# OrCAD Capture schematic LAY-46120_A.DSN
size A3; rev: 00; note: JN5189 USB DONGLE
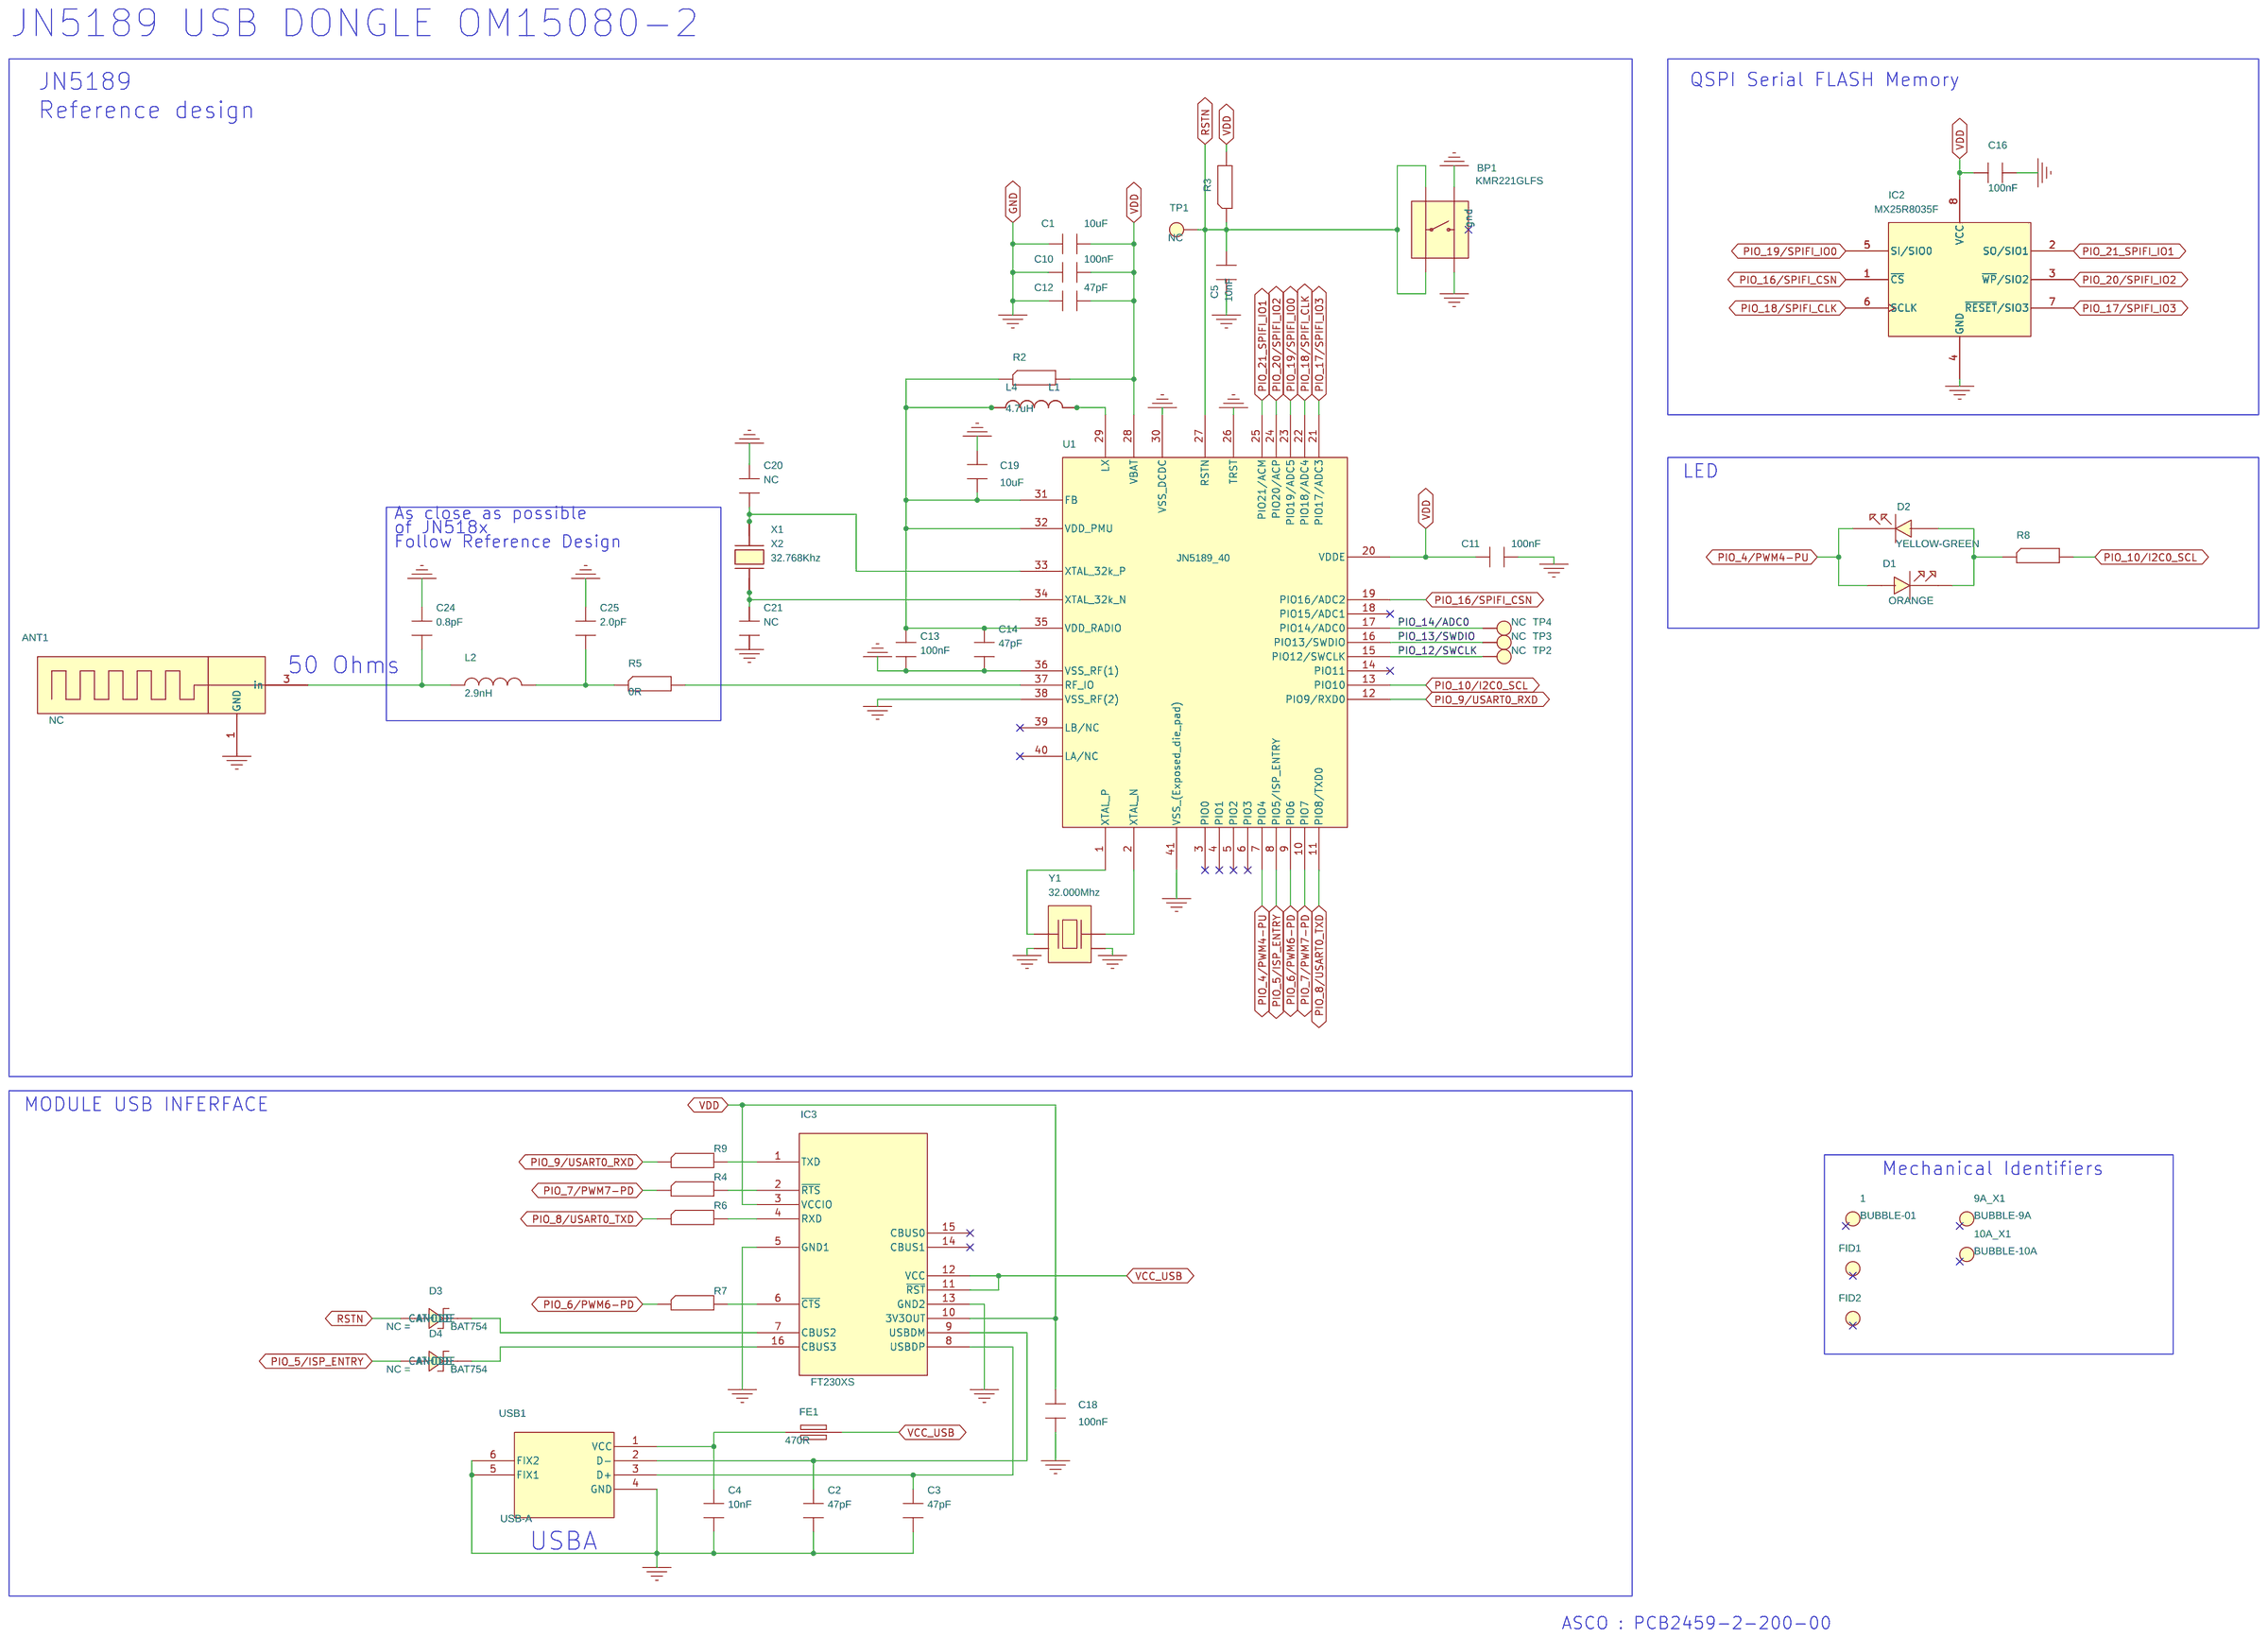
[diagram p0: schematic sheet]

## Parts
1  BUBBLE-01  [BUBBLE_DIAM8]
9A_X1  BUBBLE-9A  [BUBBLE_DIAM8]
10A_X1  BUBBLE-10A  [BUBBLE_DIAM8]
ANT1  NC  [pcb_ant_apps]
BP1  KMR221GLFS  [BP_KMR]
C1  10uF  [C0805]
C2  47pF  [C0402]
C3  47pF  [C0402]
C4  10nF  [C0402]
C5  10nF  [C0402]
C10  100nF  [C0402]
C11  100nF  [C0402]
C12  47pF  [C0402]
C13  100nF  [C0402]
C14  47pF  [C0402]
C16  100nF  [C0402]
C18  100nF  [C0402]
C19  10uF  [C0805]
C20  NC  [C0402]
C21  NC  [C0402]
C24  0.8pF  [C0402]
C25  2.0pF  [C0402]
D1  ORANGE  [LED_0603_A_K]
D2  YELLOW-GREEN  [LED_0603_A_K]
D3  BAT754  [SOT23]
D4  BAT754  [SOT23]
FE1  470R  [blm18]
FID1  NC  [FID1]
FID2  NC  [FID1]
IC2  MX25R8035F  [SOP8_127_200]
IC3  FT230XS  [jedec_mo137_ab_ssop16]
L1  4,7uH_NC  [IND_CB_2518_2520]
L2  2.9nH  [SELF_0402]
L4  4.7uH  [0805C_IPCC]
R2  NC  [R0402]
R3  2K20  [R0402]
R4  NC  [R0402]
R5  0R  [R0402]
R6  0R  [R0402]
R7  NC  [R0402]
R8  680R  [R0402]
R9  0R  [R0402]
TP1  NC  [VIA062P030]
TP2  NC  [VIA062P030]
TP3  NC  [VIA062P030]
TP4  NC  [VIA062P030]
U1  JN5189_40  [SOT618-1_HVQFN40_050_JN518x]
USB1  USB-A  [conn_usb_LUMBERG241007_A]
X1  32.768Khz_NC  [NX3215SA]
X2  32.768Khz  [NX2012SA]
Y1  32.000Mhz  [NX2016SA]

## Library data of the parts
1 = BUBBLE: Designation: Printed Circuit Board : OM15080-2 (NXP : Dongle USB board JN518x (HVQFN40)); Manufacturer_reference: PCB2459-2; Part Number: 0-CI-001591; Part Type: BUBBLE-001_CI; Supplier: ASCO
9A_X1 = BUBBLE: Designation: BOX, USB, PLUG IN, CLEAR, POLYCARBONATE; Manufacturer_reference: MULTICOMP (MCG1901); Part Number: 0-00-101542; Part Type: BUBBLE-09_MISC
10A_X1 = BUBBLE: Designation: (Protection_ESD) Clear Heatshrink 12.7mm Diameter x1m; Manufacturer_reference: Heatshrink-Online; Part Number: 0-FG-000573; Part Type: BUBBLE-10_MISC
ANT1 = ANTENNA_JN518x: Alt_Symbols: pcb_ant_apps_flip; Designation: !!! COPPER PRINTED BOARD !!!; Package: ANTENNA; Part Number: 0-00-0ANT_MOD_JN518x; Part Type: MISC
BP1 = BP_KMR: Designation: Microminiature SMT Top Actuated KMR221GLFS (KMR) - (-40°C to +85°C); Manufacturer_reference: C&K Components (KMR221GLFS); Package: KMR; Part Number: 0-00-000216; Part Type: COMMUTATOR; Temp: (-40°C to +85°C)
C1 C19 = CAPA: Alt_Symbols: 0805C; Designation: Capacitor 0805 10uF 10% 10V X7R (-55°C+125°C); Gamme: X7R; MANUFACTURER_REFERENCE: MURATA (GRM21BR71A106KA73L); Package: 805; Part Number: 0-00-306046A; Supplier: FARNELL; Tension: 10V; Tol: 10%
C2 C3 = CAPA: Alt_Symbols: 0402C; Designation: Capacitor 0402 47pF 1% 50V COG/NPO (-55°C+125°C); Gamme: COG/NPO; Package: 402; Part Number: 0-00-300163; Temp: (-55°C+125°C); Tension: 50V; Tol: 1%
C4 C5 = CAPA: Alt_Symbols: 0402C; Designation: Capacitor 0402 10nF 5% 16V X7R (-55°C+125°C); Gamme: X7R; Package: 402; Part Number: 0-00-300077; Temp: (-55°C+125°C); Tension: 16V; Tol: 5%
C10 C11 C13 C16 C18 = CAPA: Alt_Symbols: 0402C; Designation: Capacitor 0402 100nF 5% 10V X7R (-55°C+125°C); Gamme: X7R; Package: 402; Part Number: 0-00-305250; Temp: (-55°C+125°C); Tension: 10V; Tol: 5%
C12 C14 = CAPA: Alt_Symbols: 0402C; Designation: Capacitor 0402 47pF 5% 25V COG/NPO (-55°C+125°C); Gamme: COG/NPO; MANUFACTURER_REFERENCE: MURATA (GRM1555C1E470JA01); Package: 402; Part Number: 0-00-300164C; Supplier: DIGIKEY CORPORATION; Temp: (-55°C+125°C); Tension: 25V; Tol: 5%
C20 C21 = CAPA: Alt_Symbols: 0402C; Designation: !!! NOT CONNECTED !!!; Package: 402; Part Number: 0-00-3NC_C0402
C24 = CAPA: Alt_Symbols: 0402C; Designation: Capacitor 0402 0.8pF +/-0.1pF 50V; Manufacturer_reference: MURATA (GRM1555C1H0R8BA01D); Package: 402; Part Number: 0-00-306047A; Tension: 50V; Tol: +/-0.1pF
C25 = CAPA: Alt_Symbols: 0402C; Designation: Capacitor 0402 2.0pF +/-0.1pF 50V; Package: 402; Part Number: 0-00-305251; Tension: 50V; Tol: +/-0.1pF
D1 = LED: Designation: LED 0603 ORANGE ASMT-RJ45-AQ502; Manufacturer_reference: AVAGO TECHNOLOGIES (ASMT-RJ45-AQ502); Package: 0603; Part Number: 0-00-001360A; Supplier: RADIOSPARES
D2 = LED: Designation: LED 0603 YELLOW-GREEN ASMT-RF45-AN002; Manufacturer_reference: AVAGO TECHNOLOGIES (ASMT-RF45-AN002); Package: 0603; Part Number: 0-00-001359A; Supplier: FARNELL
D3 D4 = BAT754: Designation: Diode Schoktty BAT754 (SOT23); Part Number: 0-00-403888; Part Type: DIODE
FE1 = FERRITE_2: Designation: Ferrite Bead (470R - 100MHz); Manufacturer_reference: MURATA (BLM18PG471SN1D); Package: BLM18; Part Number: 0-00-000446A; Part Type: FERRITE
FID1 FID2 = MIRE: Designation: !!! Not Connected !!!; Part Number: 0-00-2MIRE_FID_NC; Part Type: MISC
IC2 = MX25R8035F_RST: Designation: Integrated Circuit QSPI Flash 8Mbit MX25R8035FM2IL0 (8-SOP); Manufacturer_reference: MACRONIX (MX25R8035FM2IL0); Package: 8-SOP; Part Number: 0-00-403917; Part Type: IC; Temp: (-40°C to +85°C)
IC3 = FT230XS: Designation: Integrated Circuit FT230XS (SSOP-16); Manufacturer_reference: FTDI Chip (FT230XS), FTDI Chip (FT230XS-R), FTDI Chip (FT230XS-U); Package: SSOP-16; Part Number: 0-00-400790; Part Type: IC
L1 = SELF: Designation: !!! NOT CONNECTED !!! Inductor 1008/2520 4,7uH 800mA(Max) 380mOhms(Max) 20%; Manufacturer_reference: TAIYO YUDEN (MBMK2520H4R7M); Package: 1008; Part Number: 0-00-002246A_NC; Part Type: INDUCTOR; Temp: (-40°C to 125°C)
L2 = SELF: Designation: Inductor 0402 2.9nH +/-0.1nH 750mA, Ron DC=70mOhms, Q=20, Resonance Freq=15.0 Ghz (-55°C to 125°C); Manufacturer_reference: MURATA (LQW15AN2N9B00); Package: 402; Part Number: 0-00-000708; Part Type: L0402; Temp: (-55°C to 125°C)
L4 = SELF: Designation: Inductor 0805 4,7uH 300mA(Max) 340mOhms(Max) 20% (-55°C to 125°C); Manufacturer_reference: TDK (MLZ2012M4R7H); Package: 805; Part Number: 0-00-002803A; Part Type: L0805; Temp: (-40°C to 125°C)
R2 R4 R7 = RES: Designation: !!! NOT CONNECTED !!!; PACKAGE: 402; Part Number: 0-00-3NC_R0402
R3 = RES: Alt_Symbols: 0402R; Designation: Resistor 0402 2K20 1% 100ppm -; PACKAGE: 402; PPM: 100ppm; Part Number: 0-00-302056; TOL: 1%; Type: CMS
R5 = RES: Alt_Symbols: 0402R; Designation: Resistor 0402 0R - - -; PACKAGE: 402; Part Number: 0-00-301956; Type: CMS
R6 R9 = RES: Alt_Symbols: 0402R; Designation: Resistor 0402 0R - - -; MANUFACTURER_REFERENCE: YAGEO (PHYCOMP) (RC0402JR-070RL); PACKAGE: 402; Part Number: 0-00-301956D; SUPPLIER: DIGIKEY CORPORATION
R8 = RES: Alt_Symbols: 0402R; Designation: Resistor 0402 680R 1% 100ppm -; PACKAGE: 402; PPM: 100ppm; Part Number: 0-00-302143; TOL: 1%; Type: CMS
TP1-TP4 = PLOT: Designation: !!! Not Connected !!!; Part Number: 0-00-2VIA062P030_NC
U1 = JN518x_QFN40: Designation: Integrated Circuit JN5189 (QFN40); Manufacturer_reference: NXP (JN5189) (QFN40); Package: HVQFN40; Part Number: 0-00-404672; Part Type: IC
USB1 = USB-A: Designation: Type-A USB connector (SMD); Manufacturer_reference: LUMBERG (2410 07); Part Number: 0-00-203197; Part Type: USB
X1 = XTAL: Designation: !!! NOT CONNECTED !!! Crystal 32.768 KHz +/-20ppm (Automotive version) (Load Cap. 12.5pF) (-40°C to 125°C); Manufacturer_reference: NDK (NX3215SA-32.768K-STD-MUS-2); Part Number: 0-00-403987_NC; Part Type: CLOCK; Temp: (-40°C to 125°C)
X2 = XTAL: Designation: Crystal 32.768 KHz +/-20ppm (Automotive version) (Load Cap. 6.0pF) (-40°C to 125°C); Manufacturer_reference: NDK (NX2012SA-32.768K-STD-MUS-2); Part Number: 0-00-404673; Part Type: CLOCK
Y1 = XTAL_NX2016_4P: Designation: Crystal 32 MHz +/-40ppm (automotive version) (Load Cap. 6.0pF) (-40°C to 125°C); Manufacturer_reference: NDK (NX2016SA 32MHZ EXS00A-CS11213 6PF); Part Number: 0-00-404674; Part Type: CLOCK

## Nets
GND: ANT1.1(GND) BP1.2 BP1.4 C1.1 C2.2 C3.2 C4.2 C5.2 C10.1 C11.2 C12.1 C13.2 C14.2 C16.1 C18.1 C19.2 C20.1 C21.2 C24.1 C25.1 IC2.4(GND) IC3.5(GND1) IC3.13(GND2) U1.26(TRST) U1.30(VSS_DCDC) U1.36(VSS_RF(1)) U1.38(VSS_RF(2)) U1.41(VSS_(Exposed_die_pad)) USB1.4(GND) USB1.5(FIX1) USB1.6(FIX2) Y1.2 Y1.4
VCC_USB: FE1.2 IC3.11(~{RST}) IC3.12(VCC)
VDD: C1.2 C10.2 C11.1 C12.2 C16.2 C18.2 IC2.8(VCC) IC3.3(VCCIO) IC3.10(3V3OUT) R2.2 R3.2 U1.20(VDDE) U1.28(VBAT)
PIO_4/PWM4-PU: D1.A D2.K U1.7(PIO4)
PIO_5/ISP_ENTRY: D4.1(ANODE) U1.8(PIO5/ISP_ENTRY)
PIO_6/PWM6-PD: R7.1 U1.9(PIO6)
PIO_7/PWM7-PD: R4.1 U1.10(PIO7)
PIO_8/USART0_TXD: R6.1 U1.11(PIO8/TXD0)
PIO_9/USART0_RXD: R9.1 U1.12(PIO9/RXD0)
PIO_10/I2C0_SCL: R8.2 U1.13(PIO10)
PIO_12/SWCLK: TP2.1 U1.15(PIO12/SWCLK)
PIO_13/SWDIO: TP3.1 U1.16(PIO13/SWDIO)
PIO_14/ADC0: TP4.1 U1.17(PIO14/ADC0)
PIO_16/SPIFI_CSN: IC2.1(~{CS}) U1.19(PIO16/ADC2)
PIO_17/SPIFI_IO3: IC2.7(~{RESET}/SIO3) U1.21(PIO17/ADC3)
PIO_18/SPIFI_CLK: IC2.6(SCLK) U1.22(PIO18/ADC4)
PIO_19/SPIFI_IO0: IC2.5(SI/SIO0) U1.23(PIO19/ADC5)
PIO_20/SPIFI_IO2: IC2.3(~{WP}/SIO2) U1.24(PIO20/ACP)
PIO_21_SPIFI_IO1: IC2.2(SO/SIO1) U1.25(PIO21/ACM)
RSTN: BP1.1 BP1.3 C5.1 D3.1(ANODE) R3.1 TP1.1 U1.27(RSTN)
N16778908: ANT1.3(in) C24.2 L2.1
N16811154: D1.K D2.A R8.1
N16827974: IC3.1(TXD) R9.2
N16827980: IC3.2(~{RTS}) R4.2
N16827994: IC3.4(RXD) R6.2
N16828020: IC3.6(~{CTS}) R7.2
N16828026: D3.3(CATHODE) IC3.7(CBUS2)
N16828032: D4.3(CATHODE) IC3.16(CBUS3)
N16828083: C3.1 IC3.8(USBDP) USB1.3(D+)
N16828101: C2.1 IC3.9(USBDM) USB1.2(D-)
N16828111: C4.1 FE1.1 USB1.1(VCC)
N16845241: C25.2 L2.2 R5.1
N16845253: U1.2(XTAL_N) Y1.3
N16845589: U1.1(XTAL_P) Y1.1
N16845609: R5.2 U1.37(RF_IO)
N16845639: C13.1 C14.1 C19.1 L1.1 L4.1 R2.1 U1.31(FB) U1.32(VDD_PMU) U1.35(VDD_RADIO)
N16845653: C20.2 U1.33(XTAL_32k_P) X1.1 X2.1
N16845667: L1.2 L4.2 U1.29(LX)
N16862787: C21.1 U1.34(XTAL_32k_N) X1.2 X2.2

Not connected (* = marked no-connect by the designer): 1 1*; 9A_X1 1*; 10A_X1 1*; BP1 5(gnd)*; FID1 1*; FID2 1*; IC3 14(CBUS1)* 15(CBUS0)*; U1 3(PIO0)* 4(PIO1)* 5(PIO2)* 6(PIO3)* 14(PIO11)* 18(PIO15/ADC1)* 39(LB/NC)* 40(LA/NC)*

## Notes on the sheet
- JN5189 USB DONGLE OM15080-2
- JN5189
- QSPI Serial FLASH Memory
- Reference design
- LED
- As close as possible
- of JN518x
- Follow Reference Design
- 50 Ohms
- MODULE USB INFERFACE
- Mechanical Identifiers
- USBA
- ASCO : PCB2459-2-200-00
